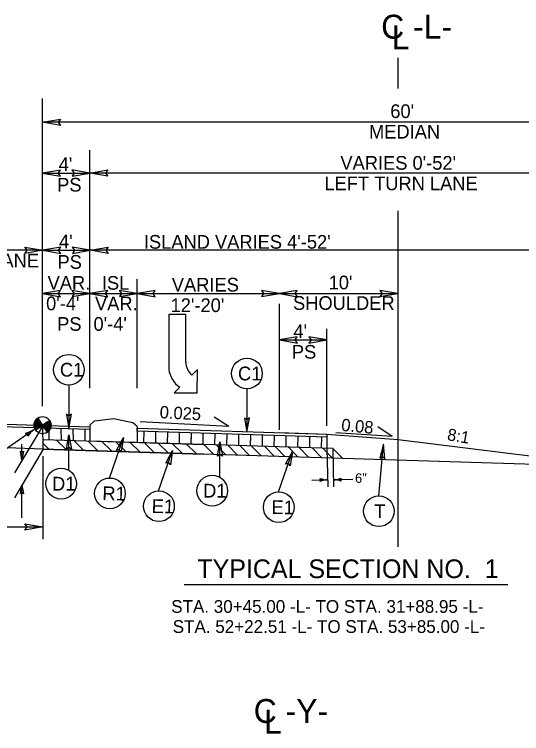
# Model space of a CAD drawing. Extents: x 2176024 to 2177225, y 75947 to 76635.
# Drawn here: x 2177006.8 to 2177049.6, y 76529 to 76589.6 of the extents above; entities that cross this region are included whole.
import ezdxf

# ---------------------------------------------------------------- set-up
doc = ezdxf.new("R2010")
doc.units = 0
for name, color, linetype in [('Exist XS Ground Line', 7, 'Continuous'), ('Old_Level_1', 7, 'Continuous'), ('Old_Level_11', 7, 'Continuous'), ('Old_Level_3', 7, 'Continuous'), ('Prop Dimension', 7, 'Continuous'), ('Prop Lane Arrow CELL', 7, 'Continuous'), ('Typical Curb CELL', 7, 'Continuous'), ('Typical Grade Point Symbol CELL', 7, 'Continuous'), ('Typical Pavement Slope CELL', 7, 'Continuous'), ('Typical Pavement Slope Information CELL', 7, 'Continuous'), ('Typical Shoulder Slope CELL', 7, 'Continuous'), ('Typical Slope Point Local CELL', 7, 'Continuous'), ('Typical Terminator CELL', 7, 'Continuous'), ('Typical Text General CELL', 7, 'Continuous'), ('Typical Text Label CELL', 7, 'Continuous')]:
    doc.layers.add(name, color=color, linetype=linetype)

msp = doc.modelspace()

# ---------------------------------------------------------------- linework, layer by layer
at = {"layer": 'Exist XS Ground Line'}
msp.add_line((2177009.267, 76552.966), (2176997.248, 76553.353), dxfattribs=at)
at = {"layer": 'Old_Level_1'}
for p, q in [((2177009.79, 76553.764), (2177009.776, 76554.713)), ((2177010.808, 76553.719), (2177010.795, 76554.684)), ((2177011.823, 76553.687), (2177011.809, 76554.646)), ((2177012.821, 76553.661), (2177012.807, 76554.613)), ((2177017.774, 76553.519), (2177017.788, 76554.478)), ((2177018.774, 76553.486), (2177018.788, 76554.45)), ((2177019.774, 76553.453), (2177019.787, 76554.418)), ((2177020.773, 76553.42), (2177020.787, 76554.38)), ((2177021.773, 76553.387), (2177021.787, 76554.357)), ((2177022.773, 76553.354), (2177022.786, 76554.334)), ((2177023.772, 76553.32), (2177023.786, 76554.285)), ((2177024.772, 76553.288), (2177024.786, 76554.26)), ((2177011.235, 76552.903), (2177010.383, 76553.737)), ((2177012.706, 76552.86), (2177011.859, 76553.69)), ((2177013.893, 76552.823), (2177013.043, 76553.655)), ((2177021.773, 76553.387), (2177021.785, 76554.242)), ((2177025.772, 76553.258), (2177025.785, 76554.227)), ((2177026.771, 76553.226), (2177026.785, 76554.192)), ((2177027.771, 76553.187), (2177027.784, 76554.162)), ((2177028.77, 76553.163), (2177028.784, 76554.128)), ((2177029.77, 76553.13), (2177029.784, 76554.104)), ((2177030.77, 76553.102), (2177030.783, 76554.072)), ((2177031.77, 76553.073), (2177031.783, 76554.039)), ((2177032.769, 76553.039), (2177032.783, 76554)), ((2177009.746, 76552.962), (2177009.267, 76553.431)), ((2177015.067, 76552.783), (2177014.212, 76553.621)), ((2177016.263, 76552.746), (2177015.416, 76553.576)), ((2177017.445, 76552.713), (2177016.6, 76553.541)), ((2177018.652, 76552.67), (2177017.793, 76553.512)), ((2177019.839, 76552.632), (2177018.977, 76553.477)), ((2177021.018, 76552.601), (2177020.165, 76553.438)), ((2177022.205, 76552.564), (2177021.353, 76553.398)), ((2177023.661, 76552.515), (2177022.858, 76553.341)), ((2177024.68, 76552.482), (2177023.868, 76553.317)), ((2177025.664, 76552.455), (2177024.854, 76553.288)), ((2177026.68, 76552.424), (2177025.869, 76553.259)), ((2177027.67, 76552.391), (2177026.863, 76553.221)), ((2177028.798, 76552.335), (2177027.967, 76553.19)), ((2177029.673, 76552.33), (2177028.866, 76553.161)), ((2177030.781, 76552.295), (2177029.968, 76553.131)), ((2177031.69, 76552.255), (2177030.868, 76553.1)), ((2177032.797, 76552.221), (2177031.978, 76553.063)), ((2177033.689, 76552.198), (2177032.869, 76553.042)), ((2177021.17, 76541.561), (2177048.492, 76541.561))]:
    msp.add_line(p, q, dxfattribs=at)
at = {"layer": 'Old_Level_11'}
for p, q in [((2177011.439, 76558.364), (2177011.439, 76554.703)), ((2177026.469, 76558.046), (2177026.469, 76554.386)), ((2177005.742, 76552.698), (2177008.525, 76554.638)), ((2177011.431, 76551.177), (2177011.431, 76554.173)), ((2177014.877, 76550.528), (2177016.059, 76553.934)), ((2177024.176, 76550.588), (2177024.176, 76553.584)), ((2177037.596, 76549.027), (2177037.995, 76553.391)), ((2177019.017, 76549.447), (2177020.199, 76552.853)), ((2177029.127, 76549.365), (2177030.309, 76552.771)), ((2177033.221, 76553.012), (2177033.287, 76549.786)), ((2177033.721, 76553), (2177033.787, 76549.774)), ((2177031.942, 76550.359), (2177033.275, 76550.387)), ((2177035.413, 76550.408), (2177033.775, 76550.374))]:
    msp.add_line(p, q, dxfattribs=at)
for points in [[(2177011.233, 76555.903), (2177011.439, 76554.703), (2177011.653, 76555.91), (2177011.439, 76555.757)], [(2177026.262, 76555.586), (2177026.469, 76554.386), (2177026.682, 76555.592), (2177026.469, 76555.439)], [(2177011.24, 76552.957), (2177011.436, 76554.159), (2177011.66, 76552.954), (2177011.445, 76553.106)], [(2177015.471, 76552.868), (2177016.059, 76553.934), (2177015.866, 76552.724), (2177015.714, 76552.939)], [(2177023.985, 76552.368), (2177024.182, 76553.57), (2177024.405, 76552.365), (2177024.191, 76552.516)], [(2177038.096, 76552.177), (2177037.995, 76553.391), (2177037.677, 76552.207), (2177037.903, 76552.341)], [(2177019.611, 76551.787), (2177020.199, 76552.853), (2177020.005, 76551.643), (2177019.854, 76551.858)], [(2177029.721, 76551.705), (2177030.309, 76552.771), (2177030.116, 76551.561), (2177029.964, 76551.776)]]:
    msp.add_lwpolyline(points, close=True, dxfattribs=at)
for centre in [(2177011.439, 76559.66), (2177026.469, 76559.342), (2177010.791, 76550.05), (2177023.537, 76549.461), (2177014.904, 76549.233), (2177019.044, 76548.152), (2177029.154, 76548.07), (2177037.6, 76547.731)]:
    msp.add_circle(centre, 1.296, dxfattribs=at)
for centre, radius, start, end in [((2177007.408, 76556.195), 1.915, 281.37373, 305.65116), ((2177007.533, 76553.947), 0.448, 14.12326, 55.65491), ((2177007.408, 76556.195), 1.942, 282.07827, 295.35269), ((2177007.408, 76556.195), 1.969, 282.65858, 291.50039), ((2177007.408, 76556.195), 1.995, 283.13909, 288.59203), ((2177007.408, 76556.195), 2.022, 283.53616, 286.18024), ((2177009.599, 76553.053), 2.022, 143.59793, 146.24201), ((2177009.599, 76553.053), 1.995, 141.18614, 146.63908), ((2177009.599, 76553.053), 1.969, 138.27778, 147.11959), ((2177009.599, 76553.053), 1.942, 134.42548, 147.6999), ((2177009.599, 76553.053), 1.915, 124.12701, 148.40444), ((2177032.308, 76550.367), 0.359, 340.40967, 21.94133), ((2177033.223, 76551.918), 1.532, 247.66015, 271.93758), ((2177033.286, 76548.854), 1.532, 90.41342, 114.69085), ((2177033.223, 76551.918), 1.554, 248.36468, 261.63911), ((2177033.286, 76548.854), 1.554, 100.71189, 113.98632), ((2177033.223, 76551.918), 1.575, 248.94499, 257.78681), ((2177033.286, 76548.854), 1.575, 104.56419, 113.40601), ((2177033.223, 76551.918), 1.596, 249.42551, 254.87844), ((2177033.286, 76548.854), 1.596, 107.47256, 112.92549), ((2177033.223, 76551.918), 1.618, 249.82257, 252.46666), ((2177033.286, 76548.854), 1.618, 109.88434, 112.52842), ((2177033.764, 76551.906), 1.532, 270.41354, 294.69097), ((2177033.827, 76548.843), 1.532, 67.66026, 91.93769), ((2177033.764, 76551.906), 1.554, 280.71201, 293.98644), ((2177033.827, 76548.843), 1.554, 68.3648, 81.63922), ((2177033.764, 76551.906), 1.575, 284.56431, 293.40612), ((2177033.827, 76548.843), 1.575, 68.94511, 77.78692), ((2177033.764, 76551.906), 1.596, 287.47267, 292.92561), ((2177033.827, 76548.843), 1.596, 69.42562, 74.87856), ((2177033.764, 76551.906), 1.618, 289.88446, 292.52854), ((2177033.827, 76548.843), 1.618, 69.82269, 72.46677), ((2177034.742, 76550.394), 0.359, 160.40979, 201.94144)]:
    msp.add_arc(centre, radius, start, end, dxfattribs=at)
at = {"layer": 'Prop Dimension'}
for p, q in [((2177039.218, 76583.373), (2177039.218, 76585.96)), ((2177009.218, 76556.58), (2177009.218, 76582.536)), ((2177069.218, 76580.525), (2177009.218, 76580.525)), ((2177013.218, 76558.096), (2177013.218, 76578.162)), ((2177009.218, 76576.241), (2177013.218, 76576.241)), ((2177065.278, 76576.236), (2177013.218, 76576.241)), ((2177039.218, 76544.74), (2177039.218, 76573.065)), ((2177009.248, 76569.728), (2176997.248, 76569.728)), ((2177009.248, 76569.728), (2177013.248, 76569.728)), ((2177065.248, 76569.734), (2177013.248, 76569.728)), ((2177017.218, 76558.096), (2177017.218, 76567.308)), ((2177009.218, 76566.082), (2177013.218, 76566.082)), ((2177013.218, 76566.082), (2177017.218, 76566.082)), ((2177017.218, 76566.082), (2177029.204, 76566.082)), ((2177029.204, 76566.082), (2177039.204, 76566.082)), ((2177029.204, 76554.583), (2177029.204, 76565.216)), ((2177033.214, 76554.942), (2177033.214, 76563.111)), ((2177029.204, 76562.173), (2177033.214, 76562.173)), ((2177009.268, 76554.981), (2177006.843, 76550.973)), ((2177007.48, 76552.048), (2177007.48, 76553.376)), ((2177009.267, 76552.966), (2177006.842, 76548.871)), ((2177009.248, 76552.359), (2177009.248, 76545.384)), ((2177007.479, 76547.17), (2177007.479, 76549.946)), ((2176985.151, 76546.409), (2177009.248, 76546.409))]:
    msp.add_line(p, q, dxfattribs=at)
at = {"layer": 'Prop Lane Arrow CELL'}
for p, q in [((2177021.315, 76564.326), (2177019.867, 76564.323)), ((2177019.867, 76564.323), (2177019.876, 76559.694)), ((2177021.323, 76560.311), (2177021.315, 76564.326)), ((2177022.289, 76559.676), (2177021.829, 76559.215)), ((2177022.271, 76557.702), (2177022.289, 76559.676)), ((2177020.8, 76558.182), (2177020.34, 76557.72)), ((2177020.34, 76557.72), (2177022.271, 76557.702))]:
    msp.add_line(p, q, dxfattribs=at)
for centre, radius, start, end in [((2177022.752, 76560.309), 1.437, 180.10633, 229.76451), ((2177022.146, 76560.045), 2.305, 188.7824, 234.0941)]:
    msp.add_arc(centre, radius, start, end, dxfattribs=at)
at = {"layer": 'Typical Curb CELL'}
for p, q in [((2177009.267, 76552.966), (2177009.248, 76554.981)), ((2177033.721, 76553.01), (2177022.821, 76553.35)), ((2177022.809, 76552.543), (2177009.267, 76552.966)), ((2177050.807, 76551.67), (2177022.809, 76552.543))]:
    msp.add_line(p, q, dxfattribs=at)
at = {"layer": 'Typical Grade Point Symbol CELL'}
for p, q in [((2177008.814, 76555.573), (2177009.226, 76554.981)), ((2177008.633, 76554.571), (2177009.226, 76554.981)), ((2177009.226, 76554.981), (2177008.633, 76554.571)), ((2177009.226, 76554.981), (2177009.817, 76555.393)), ((2177009.637, 76554.39), (2177009.226, 76554.981))]:
    msp.add_line(p, q, dxfattribs=at)
for points in [[(2177008.89, 76555.464), (2177008.547, 76555.225)], [(2177008.882, 76555.476), (2177008.556, 76555.249)], [(2177008.873, 76555.487), (2177008.566, 76555.273)], [(2177008.865, 76555.499), (2177008.579, 76555.3)], [(2177008.857, 76555.511), (2177008.593, 76555.327)], [(2177008.849, 76555.523), (2177008.609, 76555.356)], [(2177008.84, 76555.535), (2177008.629, 76555.387)], [(2177008.832, 76555.547), (2177008.656, 76555.424)], [(2177008.824, 76555.558), (2177008.69, 76555.465)], [(2177008.816, 76555.57), (2177008.751, 76555.525)], [(2177008.98, 76555.334), (2177008.504, 76555.002)], [(2177008.972, 76555.345), (2177008.505, 76555.021)], [(2177008.989, 76555.322), (2177008.505, 76554.985)], [(2177008.997, 76555.31), (2177008.505, 76554.968)], [(2177009.005, 76555.298), (2177008.505, 76554.95)], [(2177008.964, 76555.357), (2177008.506, 76555.039)], [(2177009.013, 76555.286), (2177008.506, 76554.933)], [(2177009.022, 76555.274), (2177008.507, 76554.917)], [(2177008.956, 76555.369), (2177008.509, 76555.058)], [(2177009.03, 76555.263), (2177008.509, 76554.9)], [(2177008.947, 76555.381), (2177008.511, 76555.077)], [(2177009.038, 76555.251), (2177008.511, 76554.884)], [(2177008.939, 76555.393), (2177008.513, 76555.096)], [(2177009.046, 76555.239), (2177008.514, 76554.868)], [(2177008.931, 76555.405), (2177008.517, 76555.116)], [(2177009.055, 76555.227), (2177008.517, 76554.853)], [(2177009.063, 76555.215), (2177008.52, 76554.837)], [(2177008.923, 76555.416), (2177008.522, 76555.137)], [(2177009.071, 76555.203), (2177008.523, 76554.822)], [(2177009.079, 76555.192), (2177008.526, 76554.806)], [(2177008.915, 76555.428), (2177008.527, 76555.158)], [(2177009.087, 76555.18), (2177008.53, 76554.792)], [(2177008.906, 76555.44), (2177008.533, 76555.18)], [(2177009.096, 76555.168), (2177008.534, 76554.777)], [(2177008.898, 76555.452), (2177008.539, 76555.202)], [(2177009.104, 76555.156), (2177008.539, 76554.763)], [(2177009.112, 76555.144), (2177008.544, 76554.749)], [(2177009.12, 76555.132), (2177008.549, 76554.734)], [(2177009.129, 76555.121), (2177008.554, 76554.721)], [(2177009.137, 76555.109), (2177008.56, 76554.707)], [(2177009.145, 76555.097), (2177008.565, 76554.693)], [(2177009.153, 76555.085), (2177008.571, 76554.68)], [(2177009.162, 76555.073), (2177008.578, 76554.667)], [(2177009.17, 76555.061), (2177008.583, 76554.653)], [(2177009.178, 76555.05), (2177008.59, 76554.641)], [(2177009.186, 76555.038), (2177008.597, 76554.628)], [(2177009.195, 76555.026), (2177008.604, 76554.615)], [(2177009.203, 76555.014), (2177008.612, 76554.603)], [(2177009.211, 76555.002), (2177008.619, 76554.59)], [(2177009.219, 76554.99), (2177008.628, 76554.579), (2177008.628, 76554.579)], [(2177009.821, 76555.388), (2177009.821, 76555.388), (2177009.229, 76554.976)], [(2177009.829, 76555.376), (2177009.238, 76554.964)], [(2177009.836, 76555.363), (2177009.246, 76554.952)], [(2177009.844, 76555.351), (2177009.254, 76554.94)], [(2177009.851, 76555.339), (2177009.262, 76554.929)], [(2177009.858, 76555.326), (2177009.27, 76554.917)], [(2177009.865, 76555.313), (2177009.279, 76554.905)], [(2177009.872, 76555.3), (2177009.287, 76554.893)], [(2177009.879, 76555.288), (2177009.295, 76554.881)], [(2177009.885, 76555.274), (2177009.303, 76554.869)], [(2177009.89, 76555.26), (2177009.312, 76554.858)], [(2177009.896, 76555.247), (2177009.32, 76554.846)], [(2177009.901, 76555.233), (2177009.328, 76554.834)], [(2177009.906, 76555.218), (2177009.336, 76554.822)], [(2177009.911, 76555.205), (2177009.345, 76554.81)], [(2177009.916, 76555.19), (2177009.353, 76554.798)], [(2177009.92, 76555.175), (2177009.361, 76554.787)], [(2177009.924, 76555.161), (2177009.369, 76554.775)], [(2177009.927, 76555.145), (2177009.378, 76554.763)], [(2177009.93, 76555.13), (2177009.386, 76554.751)], [(2177009.933, 76555.114), (2177009.394, 76554.739)], [(2177009.936, 76555.099), (2177009.402, 76554.727)], [(2177009.939, 76555.083), (2177009.41, 76554.716)], [(2177009.941, 76555.067), (2177009.419, 76554.704)], [(2177009.942, 76555.051), (2177009.427, 76554.692)], [(2177009.944, 76555.034), (2177009.435, 76554.68)], [(2177009.946, 76555.018), (2177009.443, 76554.668)], [(2177009.946, 76555), (2177009.452, 76554.656)], [(2177009.946, 76554.983), (2177009.46, 76554.645)], [(2177009.945, 76554.965), (2177009.468, 76554.633)], [(2177009.946, 76554.948), (2177009.476, 76554.621)], [(2177009.945, 76554.929), (2177009.485, 76554.609)], [(2177009.943, 76554.91), (2177009.493, 76554.597)], [(2177009.94, 76554.891), (2177009.501, 76554.585)], [(2177009.938, 76554.872), (2177009.509, 76554.574)], [(2177009.934, 76554.852), (2177009.518, 76554.562)], [(2177009.931, 76554.832), (2177009.526, 76554.55)], [(2177009.926, 76554.811), (2177009.534, 76554.538)], [(2177009.92, 76554.789), (2177009.542, 76554.526)], [(2177009.913, 76554.767), (2177009.55, 76554.514)], [(2177009.906, 76554.744), (2177009.559, 76554.503)], [(2177009.897, 76554.72), (2177009.567, 76554.491)], [(2177009.887, 76554.696), (2177009.575, 76554.479)], [(2177009.875, 76554.67), (2177009.583, 76554.467)], [(2177009.862, 76554.644), (2177009.592, 76554.455)], [(2177009.846, 76554.615), (2177009.6, 76554.443)], [(2177009.826, 76554.584), (2177009.608, 76554.432)], [(2177009.802, 76554.549), (2177009.616, 76554.42)], [(2177009.769, 76554.509), (2177009.625, 76554.408)], [(2177009.717, 76554.455), (2177009.633, 76554.396)]]:
    msp.add_lwpolyline(points, dxfattribs=at)
msp.add_circle((2177009.225, 76554.982), 0.721, dxfattribs=at)
for start, end in [(124.8249, 214.8249), (304.8249, 34.8249)]:
    msp.add_arc((2177009.225, 76554.982), 0.721, start, end, dxfattribs=at)
at = {"layer": 'Typical Pavement Slope CELL'}
for p, q in [((2177013.613, 76555.346), (2177015.226, 76555.535)), ((2177015.226, 76555.535), (2177016.823, 76555.224)), ((2177013.218, 76554.982), (2177013.613, 76555.346)), ((2177013.218, 76554.982), (2177013.218, 76553.646)), ((2177017.218, 76554.86), (2177016.823, 76555.224)), ((2177017.218, 76554.86), (2177017.218, 76553.524)), ((2177009.26, 76553.772), (2177022.821, 76553.349)), ((2177033.218, 76554.144), (2177033.221, 76553.012)), ((2177033.721, 76553.01), (2177034.565, 76552.177))]:
    msp.add_line(p, q, dxfattribs=at)
at = {"layer": 'Typical Pavement Slope Information CELL'}
for p, q in [((2177024.945, 76554.864), (2177023.71, 76555.668)), ((2177024.945, 76554.864), (2177017.448, 76555.264)), ((2177038.728, 76554.034), (2177033.982, 76554.348)), ((2177038.728, 76554.034), (2177037.504, 76554.854))]:
    msp.add_line(p, q, dxfattribs=at)
at = {"layer": 'Typical Shoulder Slope CELL'}
for p, q in [((2177029.218, 76554.358), (2177033.218, 76554.221)), ((2177033.218, 76554.221), (2177039.22, 76553.763)), ((2177039.22, 76553.763), (2177050.807, 76552.356)), ((2177009.267, 76552.966), (2177022.809, 76552.543))]:
    msp.add_line(p, q, dxfattribs=at)
at = {"layer": 'Typical Slope Point Local CELL'}
msp.add_line((2177022.818, 76553.35), (2177013.218, 76553.649), dxfattribs=at)
for points in [[(2176969.284, 76554.939), (2176997.248, 76555.355), (2177013.218, 76554.857), (2177013.218, 76554.607), (2176997.248, 76555.105), (2176969.283, 76554.689)], [(2177017.218, 76554.732), (2177033.218, 76554.221), (2177033.218, 76553.983), (2177017.218, 76554.482)]]:
    msp.add_lwpolyline(points, close=True, dxfattribs=at)
at = {"layer": 'Typical Terminator CELL'}
for points in [[(2177010.728, 76580.265), (2177009.218, 76580.525), (2177010.736, 76580.793), (2177010.543, 76580.525)], [(2177010.728, 76576.501), (2177009.218, 76576.241), (2177010.736, 76575.973), (2177010.543, 76576.241)], [(2177011.709, 76575.981), (2177013.218, 76576.241), (2177011.7, 76576.509), (2177011.893, 76576.241)], [(2177014.728, 76575.981), (2177013.218, 76576.241), (2177014.736, 76576.509), (2177014.543, 76576.241)], [(2177007.738, 76569.988), (2177009.248, 76569.728), (2177007.73, 76569.46), (2177007.923, 76569.728)], [(2177010.758, 76569.988), (2177009.248, 76569.728), (2177010.766, 76569.46), (2177010.573, 76569.728)], [(2177011.738, 76569.468), (2177013.248, 76569.728), (2177011.73, 76569.997), (2177011.923, 76569.728)], [(2177014.758, 76569.468), (2177013.248, 76569.728), (2177014.766, 76569.997), (2177014.573, 76569.728)], [(2177010.728, 76566.342), (2177009.218, 76566.082), (2177010.736, 76565.814), (2177010.543, 76566.082)], [(2177011.709, 76565.822), (2177013.218, 76566.082), (2177011.7, 76566.351), (2177011.893, 76566.082)], [(2177014.728, 76566.342), (2177013.218, 76566.082), (2177014.736, 76565.814), (2177014.543, 76566.082)], [(2177015.709, 76565.822), (2177017.218, 76566.082), (2177015.7, 76566.351), (2177015.893, 76566.082)], [(2177018.728, 76566.342), (2177017.218, 76566.082), (2177018.736, 76565.814), (2177018.543, 76566.082)], [(2177027.694, 76565.822), (2177029.204, 76566.082), (2177027.686, 76566.351), (2177027.878, 76566.082)], [(2177030.713, 76566.342), (2177029.204, 76566.082), (2177030.722, 76565.814), (2177030.529, 76566.082)], [(2177037.694, 76565.822), (2177039.204, 76566.082), (2177037.686, 76566.351), (2177037.878, 76566.082)], [(2177030.713, 76562.433), (2177029.204, 76562.173), (2177030.722, 76561.905), (2177030.529, 76562.173)], [(2177031.704, 76561.913), (2177033.214, 76562.173), (2177031.696, 76562.441), (2177031.889, 76562.173)], [(2177007.612, 76552.802), (2177007.48, 76552.048), (2177007.348, 76552.807), (2177007.482, 76552.71)], [(2177007.347, 76549.192), (2177007.479, 76549.946), (2177007.611, 76549.187), (2177007.477, 76549.284)], [(2177007.738, 76546.669), (2177009.248, 76546.409), (2177007.73, 76546.14), (2177007.923, 76546.409)]]:
    msp.add_lwpolyline(points, close=True, dxfattribs=at)

# ---------------------------------------------------------------- texts
at = {"layer": 'Old_Level_11'}
for s, height, rotation, p in [('C1', 1.16, 0.00026, (2177010.683, 76559.08)), ('C1', 1.16, 0.00026, (2177025.713, 76558.762)), ('D1', 1.16, 0.00026, (2177010.018, 76549.47)), ('6"', 0.8051, 358.8245, (2177035.587, 76550.127)), ('D1', 1.16, 0.00026, (2177022.764, 76548.881)), ('R1', 1.16, 358.82491, (2177014.256, 76548.666)), ('E1', 1.16, 358.82491, (2177018.417, 76547.584)), ('E1', 1.16, 358.82491, (2177028.527, 76547.502)), ('T', 1.16, 359.85674, (2177037.217, 76547.152))]:
    msp.add_text(s, height=height, rotation=rotation, dxfattribs=at).set_placement(p)
at = {"layer": 'Old_Level_3'}
msp.add_text('TYPICAL SECTION NO.  1', height=1.5766, rotation=0.00002, dxfattribs=at).set_placement((2177022.283, 76542.089))
at = {"layer": 'Typical Pavement Slope Information CELL'}
for s, rotation, p in [('0.025', 356.94501, (2177019.085, 76555.578)), ('0.08', 354.76446, (2177034.395, 76554.504))]:
    msp.add_text(s, height=1.0429, rotation=rotation, dxfattribs=at).set_placement(p)
at = {"layer": 'Typical Slope Point Local CELL'}
msp.add_text('8:1', height=1.0064, rotation=350.16835, dxfattribs=at).set_placement((2177043.32, 76553.732))
at = {"layer": 'Typical Text General CELL'}
for s, height, p in [("60'", 1.1533, (2177038.565, 76580.884)), ('MEDIAN', 1.1533, (2177036.772, 76579.154)), ("4'", 1.1533, (2177010.58, 76576.413)), ("VARIES 0'-52' ", 1.15334, (2177034.355, 76576.525)), ('PS', 1.1533, (2177010.451, 76574.683)), ('LEFT TURN LANE', 1.15334, (2177033.001, 76574.795)), ("4'", 1.1533, (2177010.61, 76569.9)), ("ISLAND VARIES 4'-52'", 1.15334, (2177017.774, 76569.866)), ('TRAVEL LANE', 1.15334, (2176998.467, 76568.287)), ('PS', 1.1533, (2177010.481, 76568.17)), ("10'", 1.1533, (2177033.362, 76566.439)), ('VAR. ', 1.1533, (2177009.647, 76566.405)), ('ISL ', 1.1533, (2177014.227, 76566.405)), ('VARIES ', 1.1533, (2177020.13, 76566.254)), ("0'-4'", 1.1533, (2177009.519, 76564.675)), ('VAR. ', 1.1533, (2177013.647, 76564.675)), ('SHOULDER', 1.1533, (2177030.361, 76564.709)), ("12'-20'", 1.1533, (2177020.028, 76564.524)), ('PS', 1.1533, (2177010.451, 76562.945)), ("0'-4'", 1.1533, (2177013.519, 76562.945)), ("4'", 1.1533, (2177030.388, 76562.322)), ('PS', 1.1533, (2177030.259, 76560.592))]:
    msp.add_text(s, height=height, dxfattribs=at).set_placement(p)
at = {"layer": 'Typical Text Label CELL'}
for s, height, p in [('C -L- ', 2.0131, (2177037.797, 76587.579)), ('STA. 30+45.00 -L- TO STA. 31+88.95 -L-', 1.0742, (2177020.077, 76539.162)), ('STA. 52+22.51 -L- TO STA. 53+85.00 -L-', 1.0742, (2177020.205, 76537.468)), ('C -Y- ', 2.0131, (2177027.041, 76529.88))]:
    msp.add_text(s, height=height, dxfattribs=at).set_placement(p)
for p in [(2177038.675, 76586.678), (2177027.919, 76528.979)]:
    msp.add_text('L', height=2.013, rotation=359.9469, dxfattribs=at).set_placement(p)

doc.saveas('drawing.dxf')
